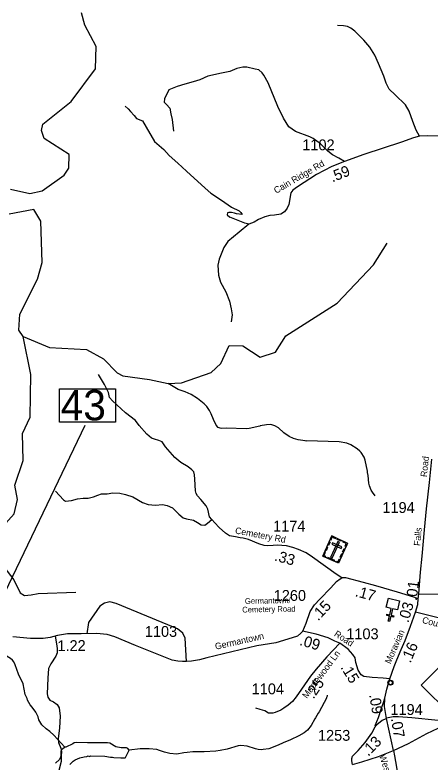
# Model space of a CAD drawing. Extents: x 1248089 to 1457196, y 820910 to 988753.
# Drawn here: x 1350937 to 1355719, y 860169 to 868771 of the extents above; entities that cross this region are included whole.
import ezdxf

# ---------------------------------------------------------------- set-up
doc = ezdxf.new("R2010")
doc.units = 0
for name, color, linetype in [('Exist Civil Demographics Community CELL', 7, 'Continuous'), ('Exist Cultural Cemetery CELL', 7, 'Continuous'), ('Exist Cultural Church CELL', 7, 'Continuous'), ('Exist Hydrographic Creek Single Shore', 7, 'Continuous'), ('Exist Hydrographic Misc Water Feature', 7, 'Continuous'), ('Exist Road Non-System Type 51', 7, 'Continuous'), ('Exist Road Primary NC Attributed', 7, 'Continuous'), ('Exist Road Primary NC Shield CELL', 7, 'Continuous'), ('Exist Road Secondary Structure Standard Bridge Number Label', 7, 'Continuous'), ('Exist Road Secondary Type 10 Attributed', 7, 'Continuous'), ('Exist Road Secondary Type 51 Attributed', 7, 'Continuous'), ('Exist Road Secondary Type 51 Label', 7, 'Continuous'), ('Prop GRAU CAT1 Cell', 7, 'Continuous'), ('Prop Lane Lines', 7, 'Continuous')]:
    doc.layers.add(name, color=color, linetype=linetype)

msp = doc.modelspace()

# ---------------------------------------------------------------- linework, layer by layer
at = {"layer": 'Exist Civil Demographics Community CELL'}
msp.add_lwpolyline([(1355238.4, 861087.2), (1355238.7, 861088.9), (1355239.2, 861090.9), (1355240.1, 861093.1), (1355241, 861094.8), (1355242, 861096.6), (1355243.2, 861098.2), (1355244.4, 861099.5), (1355245.8, 861100.9), (1355247.5, 861102.3), (1355249.1, 861103.4), (1355250.6, 861104.3), (1355252.1, 861105), (1355253.8, 861105.7), (1355255.5, 861106.3), (1355256.8, 861106.6), (1355258.3, 861106.8), (1355259.6, 861107.1), (1355261.5, 861107.2), (1355262.9, 861107.1), (1355264.6, 861107), (1355266.1, 861106.8), (1355267.6, 861106.5), (1355269.1, 861106.1), (1355270.7, 861105.5), (1355272.7, 861104.6), (1355274.6, 861103.5), (1355276.2, 861102.5), (1355277.7, 861101.2), (1355278.7, 861100.3), (1355280, 861098.9), (1355281.2, 861097.5), (1355282.1, 861096.1), (1355283.1, 861094.6), (1355283.8, 861093), (1355284.4, 861091.5), (1355284.9, 861090), (1355285.3, 861088.6), (1355285.6, 861086.7), (1355285.8, 861085.3), (1355285.9, 861083.5), (1355285.9, 861081.7), (1355285.7, 861080), (1355285.4, 861078.3), (1355284.9, 861076.4), (1355284.3, 861074.6), (1355283.6, 861073.1), (1355282.7, 861071.3), (1355281.7, 861069.6), (1355280.6, 861068.2), (1355279.3, 861066.8), (1355277.7, 861065.2), (1355276.2, 861064), (1355274.6, 861062.9), (1355273.3, 861062.2), (1355271.3, 861061.2), (1355269.1, 861060.4), (1355267.3, 861059.9), (1355265.2, 861059.5), (1355263.9, 861059.4), (1355262.5, 861059.3), (1355260.8, 861059.3), (1355259.5, 861059.4), (1355257.8, 861059.6), (1355256, 861060), (1355254.6, 861060.4), (1355253, 861061), (1355251.6, 861061.6), (1355250.4, 861062.3), (1355248.4, 861063.5), (1355246.7, 861064.8), (1355245.2, 861066.2), (1355243.8, 861067.7), (1355242.8, 861068.9), (1355241.9, 861070.2), (1355240.7, 861072.3), (1355240.2, 861073.4), (1355239.6, 861074.6), (1355238.8, 861077.1), (1355238.4, 861079.3), (1355238.2, 861080.9), (1355238.1, 861082.8), (1355238, 861084.2), (1355238.2, 861086.2)], close=True, dxfattribs=at)
msp.add_lwpolyline([(1355238.4, 861087.2), (1355238.7, 861088.9), (1355239.2, 861090.9), (1355240.1, 861093.1), (1355241, 861094.8), (1355242, 861096.6), (1355243.2, 861098.2), (1355244.4, 861099.5), (1355245.8, 861100.9), (1355247.5, 861102.3), (1355249.1, 861103.4), (1355250.6, 861104.3), (1355252.1, 861105), (1355253.8, 861105.7), (1355255.5, 861106.3), (1355256.8, 861106.6), (1355258.3, 861106.8), (1355259.6, 861107.1), (1355261.5, 861107.2), (1355262.9, 861107.1), (1355264.6, 861107), (1355266.1, 861106.8), (1355267.6, 861106.5), (1355269.1, 861106.1), (1355270.7, 861105.5), (1355272.7, 861104.6), (1355274.6, 861103.5), (1355276.2, 861102.5), (1355277.7, 861101.2), (1355278.7, 861100.3), (1355280, 861098.9), (1355281.2, 861097.5), (1355282.1, 861096.1), (1355283.1, 861094.6), (1355283.8, 861093), (1355284.4, 861091.5), (1355284.9, 861090), (1355285.3, 861088.6), (1355285.6, 861086.7), (1355285.8, 861085.3), (1355285.9, 861083.5), (1355285.9, 861081.7), (1355285.7, 861080), (1355285.4, 861078.3), (1355284.9, 861076.4), (1355284.3, 861074.6), (1355283.6, 861073.1), (1355282.7, 861071.3), (1355281.7, 861069.6), (1355280.6, 861068.2), (1355279.3, 861066.8), (1355277.7, 861065.2), (1355276.2, 861064), (1355274.6, 861062.9), (1355273.3, 861062.2), (1355271.3, 861061.2), (1355269.1, 861060.4), (1355267.3, 861059.9), (1355265.2, 861059.5), (1355263.9, 861059.4), (1355262.5, 861059.3), (1355260.8, 861059.3), (1355259.5, 861059.4), (1355257.8, 861059.6), (1355256, 861060), (1355254.6, 861060.4), (1355253, 861061), (1355251.6, 861061.6), (1355250.4, 861062.3), (1355248.4, 861063.5), (1355246.7, 861064.8), (1355245.2, 861066.2), (1355243.8, 861067.7), (1355242.8, 861068.9), (1355241.9, 861070.2), (1355240.7, 861072.3), (1355240.2, 861073.4), (1355239.6, 861074.6), (1355238.8, 861077.1), (1355238.4, 861079.3), (1355238.2, 861080.9), (1355238.1, 861082.8), (1355238, 861084.2), (1355238.2, 861086.2)], close=True, dxfattribs=at)
for centre, radius in [((1355262, 861083.4), 28.8), ((1355262, 861083.4), 28.8), ((1355261.9, 861083.5), 23.4), ((1355261.9, 861083.5), 23.4)]:
    msp.add_circle(centre, radius, dxfattribs=at)
at = {"layer": 'Exist Cultural Cemetery CELL'}
for points in [[(1354587.1, 862773), (1354768.6, 862691.1), (1354663.9, 862459), (1354482.5, 862540.9)], [(1354569.3, 862733.5), (1354579.7, 862728.8), (1354592.9, 862758.2), (1354629.9, 862741.5), (1354634.5, 862751.7), (1354587.1, 862773)], [(1354538.8, 862665.9), (1354556.6, 862705.4), (1354567, 862700.7), (1354549.2, 862661.2)], [(1354674.5, 862701.5), (1354657.4, 862709.1), (1354574.1, 862524.3), (1354591.1, 862516.6)], [(1354596.4, 862694.2), (1354588.7, 862677.2), (1354696, 862628.7), (1354703.7, 862645.8)], [(1354654.6, 862742.5), (1354701.9, 862721.2), (1354697.2, 862710.8), (1354650, 862732.1)], [(1354750.9, 862651.6), (1354740.5, 862656.3), (1354753.7, 862685.6), (1354716.8, 862702.3), (1354721.3, 862712.4), (1354768.7, 862691.1)], [(1354512.6, 862527.3), (1354517.3, 862537.8), (1354497.3, 862546.8), (1354513.9, 862583.7), (1354503.8, 862588.3), (1354482.4, 862541)], [(1354511.2, 862604.7), (1354529, 862644.1), (1354539.4, 862639.5), (1354521.6, 862600)], [(1354710.4, 862589.7), (1354728.2, 862629.1), (1354738.6, 862624.5), (1354720.8, 862585)], [(1354539.5, 862527.7), (1354616.9, 862492.8), (1354612.2, 862482.4), (1354534.9, 862517.3)], [(1354633.7, 862472.7), (1354638.5, 862483.1), (1354658.5, 862474.1), (1354675.1, 862510.9), (1354685.3, 862506.3), (1354663.9, 862459)], [(1354683.3, 862529.6), (1354701.1, 862569.1), (1354711.5, 862564.4), (1354693.7, 862524.9)]]:
    msp.add_lwpolyline(points, close=True, dxfattribs=at)
at = {"layer": 'Exist Cultural Church CELL'}
msp.add_lwpolyline([(1355342.2, 861922.1), (1355286.7, 861934.8), (1355269.6, 861860.6), (1355300.8, 861853.4), (1355297.2, 861837.8), (1355266, 861845), (1355252.6, 861786.4), (1355236.9, 861790), (1355250.4, 861848.6), (1355219.2, 861855.8), (1355222.8, 861871.3), (1355254, 861864.2), (1355271.1, 861938.4), (1355214.9, 861951.4), (1355238.7, 862055.1), (1355366, 862025.9)], close=True, dxfattribs=at)
at = {"layer": 'Exist Hydrographic Creek Single Shore'}
for points in [[(1350885.2, 866764.1), (1351109.2, 866716.9), (1351252.2, 866747), (1351506.2, 866925.7), (1351558.3, 867006.7), (1351561.2, 867164.1), (1351273.2, 867347.2), (1351242.2, 867439.7), (1351260.2, 867514.9), (1351583.2, 867774.4), (1351866.2, 868149.5), (1351872.2, 868408.7), (1351744.2, 868654.1), (1351705.2, 868796.1)], [(1351031.3, 865067.3), (1350983.2, 865143.7), (1350995.2, 865327.3), (1351196.2, 865730.3), (1351250.3, 865919.7), (1351235.2, 866396), (1351155.2, 866532.2), (1350870.2, 866478.7)], [(1351031.3, 865067.3), (1351337.2, 864942.9), (1351762.3, 864917.9), (1351959.2, 864812.2), (1352114.3, 864651.5), (1352180.3, 864617.4), (1352488.3, 864575), (1352701.2, 864526.8), (1352854.3, 864534.9), (1353198.3, 864652.7), (1353309.3, 864758.9), (1353405.3, 864963.7), (1353564.3, 864960.5), (1353761.2, 864831.9), (1353937.3, 864887.3), (1354058.3, 865075.4), (1354650.3, 865454.1), (1355068.3, 865895.5), (1355224.3, 866141.8)], [(1350118.3, 862209.9), (1350114.3, 862410.2), (1350191.3, 862533.3), (1350379.2, 862729.8), (1350522.2, 862792.6), (1350765.2, 862846.9), (1350928.2, 863027.4), (1350965.2, 863190.7), (1350935.2, 863358.9), (1351033.2, 863642.5), (1351023.3, 863951.2), (1351111.2, 864139.8), (1351122.2, 864632), (1351031.3, 865067.3)]]:
    msp.add_lwpolyline(points, dxfattribs=at)
at = {"layer": 'Exist Hydrographic Misc Water Feature'}
for points in [[(1355088.6, 863236.1), (1355055.6, 863276.9), (1355040.1, 863301.2), (1355021.2, 863349.7), (1355014, 863381.8), (1355005.9, 863470), (1354998.7, 863502.1), (1354999, 863518.1), (1354972, 863646.8), (1354958.6, 863679.1), (1354925.9, 863733.8), (1354910.2, 863750.2), (1354878.9, 863777), (1354807.8, 863820.7), (1354760.4, 863841.8), (1354672.6, 863855.8), (1354294.8, 863866.9), (1354288.7, 863865), (1354280.8, 863869.2), (1354201, 863879.1), (1354145.4, 863894.4), (1354097.8, 863917.5), (1354034.9, 863961), (1353972.1, 864018.5), (1353932.6, 864039.4), (1353884.9, 864054.6), (1353836.9, 864053.7), (1353762.6, 864041.5), (1353756.5, 864037.7), (1353635.8, 864010.5), (1353603.8, 864007.3), (1353371.8, 864014.8), (1353315.8, 864010.1), (1353299.8, 864012.6), (1353278, 864023), (1353256.6, 864047.5), (1353224.1, 864112.3), (1353199.5, 864176.9), (1353180.4, 864217.3), (1353149.5, 864264.1), (1353118.2, 864294.8), (1353039.6, 864356.7), (1352968.6, 864402.4), (1352897.2, 864432.1), (1352817.8, 864460), (1352701.2, 864526.8)], [(1351511.8, 860340.9), (1351387.2, 860478.5), (1351340.2, 860521.7), (1351298.9, 860552.6), (1351247.9, 860599.8), (1351234.3, 860616.2), (1351211.2, 860656.7), (1351203.9, 860688.9), (1351177.2, 860745.5), (1351134.5, 860802.5), (1351111, 860827.1), (1351080.3, 860883.8), (1351076.7, 860899.9), (1351055.8, 860948.4), (1351030.6, 861069), (1350977, 861182.3), (1350941.5, 861287), (1350924.2, 861323.4), (1350910.7, 861341.8), (1350887.1, 861362.3), (1350816.1, 861404.3)], [(1354532.4, 860937.6), (1354534.3, 860929.5), (1354525.9, 860913.7), (1354525.7, 860905.7), (1354442.1, 860747.7), (1354429.7, 860732.1), (1354400.5, 860676.8), (1354392.3, 860668.9), (1354350.5, 860590), (1354309.2, 860537), (1354268.5, 860505.9), (1354207.7, 860469.4), (1354110.6, 860423.7), (1354027.9, 860391.7), (1353971.2, 860363), (1353860.3, 860321.6), (1353796.1, 860313.1), (1353772, 860311.8), (1353740.1, 860314.5), (1353708.2, 860321.2), (1353613, 860353.5), (1353541.1, 860361.2), (1353507, 860356.1), (1353380.1, 860319.1), (1353299.7, 860301), (1353251.5, 860294.2), (1353115.3, 860287.4), (1352987.3, 860288.4), (1352923.1, 860278), (1352883, 860274.9), (1352802.6, 860260.8), (1352722.7, 860266.8), (1352659.1, 860282.3), (1352603.5, 860303.6), (1352571.7, 860312.3), (1352484, 860322.5), (1352379.9, 860320.9), (1352253.6, 860306.6)], [(1352253.6, 860306.6), (1352238, 860326.3), (1352222.1, 860332.6), (1352160.1, 860332.1), (1352100.3, 860343.6), (1352029.3, 860385.2), (1352005.4, 860391.8), (1351773.4, 860391.4), (1351645.4, 860396.4), (1351621.3, 860391), (1351605, 860379.4), (1351524.1, 860341.3), (1351511.8, 860340.9)], [(1351511.8, 860340.9), (1351506, 860333.7), (1351475.4, 860308.4), (1351465.1, 860292.7), (1351464.6, 860270.7), (1351471.1, 860206.6), (1351469, 860200.7), (1351470.4, 860174.6), (1351442, 860071.3)], [(1351571.6, 860140.2), (1351606.4, 860179.3), (1351632.9, 860196.7), (1351683.4, 860219.5), (1351733.7, 860230.3), (1351765.8, 860233.6), (1351781.9, 860239.1), (1351797.8, 860234.8), (1351811.9, 860240.4), (1351973.9, 860236.6), (1352037.7, 860227.1), (1352061.7, 860226.5), (1352077.6, 860222.1), (1352157.4, 860216.3), (1352205.5, 860219.1), (1352211.6, 860221), (1352253.6, 860306.6)]]:
    msp.add_lwpolyline(points, dxfattribs=at)
at = {"layer": 'Exist Road Non-System Type 51'}
for points in [[(1355599.1, 867375.3), (1355557.9, 867446.4), (1355518.9, 867545.6), (1355479.8, 867662.8), (1355437.8, 867735), (1355317.7, 867852.2), (1355248.6, 867918.3), (1355212.5, 867984.4), (1355185.5, 868065.6), (1355125.4, 868212.9), (1355083.4, 868309), (1355026.3, 868399.2), (1354954.3, 868480.4), (1354852.1, 868585.6), (1354807.1, 868618.6), (1354768, 868636.6), (1354723, 868645.7), (1354653.9, 868648.7)], [(1354733.8, 867085.4), (1354669.4, 867120.3), (1354594.3, 867162.4), (1354540.2, 867204.5), (1354456.1, 867288.7), (1354372, 867348.8), (1354336, 867366.8), (1354170.8, 867429.9), (1354092.7, 867484), (1354032.6, 867583.2), (1353966.6, 867715.4), (1353852.4, 867989), (1353804.4, 868076.1), (1353783.4, 868106.2), (1353747.3, 868139.2), (1353705.3, 868148.2), (1353609.6, 868171.1), (1353561.6, 868168.1), (1353492.5, 868153.1), (1353414.4, 868120), (1353297.3, 868095.9), (1353246.2, 868083.9), (1353159.1, 868065.9), (1353066, 868023.8), (1352990.9, 868002.8), (1352894.8, 867975.7), (1352807.7, 867945.7), (1352711.6, 867909.6), (1352660.6, 867804.4), (1352657.6, 867768.3), (1352684.6, 867741.3), (1352720.6, 867699.2), (1352732.6, 867633.1), (1352747.7, 867567), (1352765.7, 867431.7)], [(1352207.1, 867721.4), (1352243.1, 867688.4), (1352267.1, 867661.3), (1352312.2, 867613.2), (1352336.2, 867577.2), (1352405.3, 867553.1), (1352450.3, 867478), (1352543.4, 867315.7), (1352651.6, 867222.5), (1352714.6, 867153.4), (1352813.7, 867066.2), (1352912.9, 866973), (1353129.1, 866777.7), (1353194.6, 866718.9), (1353317.7, 866637.7), (1353431.9, 866559.6), (1353522, 866514.5), (1353540, 866496.4), (1353555, 866475.4)], [(1353555, 866475.4), (1353488.9, 866481.4), (1353464.9, 866490.4), (1353431.9, 866496.4), (1353401.8, 866496.4), (1353386.8, 866493.4), (1353380.8, 866469.4), (1353413.1, 866442)], [(1353631, 866363.9), (1353519.2, 866269.8), (1353390.1, 866161.6), (1353345, 866095.5), (1353290.9, 865960.3), (1353272.9, 865891.1), (1353281.9, 865773.9), (1353306, 865695.8), (1353366, 865584.6), (1353408.1, 865476.4), (1353429.1, 865389.2), (1353438.1, 865320.1), (1353429.1, 865235.9)], [(1353178.6, 862991.1), (1353159.5, 863080.2), (1353141.8, 863120.1), (1353077.6, 863190.9), (1353040, 863235.2), (1353024.5, 863259.6), (1353017.9, 863292.8), (1353011.2, 863425.7), (1353006.8, 863474.4), (1352997.9, 863509.9), (1352973.6, 863534.2), (1352933.8, 863569.7), (1352849.7, 863618.4), (1352778.8, 863676), (1352672.6, 863797.8), (1352633.1, 863854.5), (1352593.3, 863872.2), (1352546.8, 863885.5), (1352511.4, 863896.6), (1352456, 863943.1), (1352369.7, 864042.8), (1352327.7, 864100.4), (1352212.6, 864189), (1352060.5, 864329.5), (1352027.3, 864365), (1352016.2, 864422.5), (1351967.5, 864515.6), (1351901.1, 864630.7)], [(1351405.2, 863286.8), (1351498.1, 863187.1), (1351518, 863173.8), (1351588.8, 863180.5), (1351657.5, 863200.4), (1351721.6, 863207), (1351781.4, 863207), (1351827.9, 863218.1), (1351841.2, 863224.8), (1351892.1, 863242.5), (1351936.3, 863258), (1351998.3, 863255.8), (1352064.7, 863269.1), (1352144.4, 863264.6), (1352210.8, 863249.1), (1352297.1, 863224.8), (1352407.7, 863156.1), (1352471.9, 863134), (1352556, 863125.1), (1352635.7, 863134), (1352691, 863122.9), (1352753, 863096.3), (1352826, 863023.2), (1352875.7, 862981.4), (1352913.3, 862968.1), (1352995.2, 862952.6), (1353041.7, 862926), (1353083.7, 862899.5), (1353123.5, 862897.2), (1353154.5, 862919.4), (1353205.4, 862961.5)], [(1350660.7, 862252.6), (1350657.9, 862426.4), (1350661.3, 862457.2), (1350695.4, 862467.4), (1350763.6, 862460.6), (1350811.4, 862416.2), (1350923.9, 862266), (1350999, 862115.8), (1351046.7, 862085.1), (1351125.2, 862095.3), (1351203.7, 862109), (1351640.3, 862126)], [(1352913.3, 861328), (1352898.4, 861597.1), (1352871.1, 861655.2), (1352809.7, 861702.9), (1352103.6, 861996.5), (1352028.6, 862013.6), (1351970.6, 861999.9), (1351916, 861962.4), (1351783, 861774.6), (1351765.9, 861644.9)], [(1351400.4, 861619.1), (1351417.5, 861530.8), (1351424.9, 861476.8), (1351422.4, 861427.8), (1351407.7, 861388.6), (1351351.4, 861300.3), (1351324.4, 861246.4), (1351314.6, 861133.6), (1351309.7, 860954.6), (1351314.6, 860915.3), (1351339.1, 860881), (1351380.8, 860861.4), (1351422.4, 860832), (1351446.9, 860795.2), (1351459.2, 860697.1), (1351451.8, 860562.2), (1351437.1, 860437.2), (1351439.6, 860395.5), (1351466.5, 860329.3), (1351473.9, 860287.6), (1351471.4, 860245.9), (1351449.4, 860196.9), (1351405.3, 860157.6)], [(1355088.2, 860588.4), (1355125.4, 860683.5), (1355161.2, 860788.6), (1355181.1, 860856.6), (1355196.6, 860903.9)], [(1356091.9, 860630.9), (1355812.5, 860648.8), (1355510.7, 860680.1), (1355354.2, 860691.3), (1355293.9, 860689.1), (1355217.9, 860673.4)]]:
    msp.add_lwpolyline(points, dxfattribs=at)
at = {"layer": 'Exist Road Primary NC Attributed'}
for points in [[(1355298.7, 860301.7), (1355470, 860382.6), (1355681.8, 860499), (1355811.2, 860558.3), (1355897.6, 860588.5), (1356022.4, 860613.2), (1356097.9, 860617.4), (1356169.5, 860613.8), (1356318.9, 860597.6)], [(1354827.3, 860141.6), (1354933, 860173.1), (1355123.6, 860231.6), (1355298.7, 860301.7)]]:
    msp.add_lwpolyline(points, dxfattribs=at)
at = {"layer": 'Exist Road Primary NC Shield CELL'}
msp.add_lwpolyline([(1355616.4, 861055.9), (1355949.4, 861388.9), (1356282.4, 861055.9), (1355949.4, 860722.9)], close=True, dxfattribs=at)
at = {"layer": 'Exist Road Secondary Structure Standard Bridge Number Label'}
msp.add_line((1350655.5, 861776.7), (1351747.8, 864049.4), dxfattribs=at)
msp.add_lwpolyline([(1351451.8, 864465.9), (1352095.9, 864465.9), (1352095.9, 864083.6), (1351451.8, 864083.6)], close=True, dxfattribs=at)
at = {"layer": 'Exist Road Secondary Type 10 Attributed'}
msp.add_lwpolyline([(1354138.1, 862639.6), (1354066.8, 862659.2), (1353959, 862667), (1353912.1, 862662.3), (1353851.1, 862659.2), (1353807.4, 862662.3), (1353746.4, 862681.1), (1353627.7, 862731.1), (1353565.2, 862748.3), (1353532.3, 862751.5), (1353477.7, 862760.8), (1353408.9, 862774.9), (1353362, 862804.6), (1353291.7, 862870.3), (1353240.1, 862923.5), (1353205.4, 862961.5), (1353178.6, 862991.1)], dxfattribs=at)
at = {"layer": 'Exist Road Secondary Type 51 Attributed'}
for points in [[(1355811.6, 867375.3), (1355690.5, 867380.7), (1355599.1, 867375.3), (1355526.4, 867356.5), (1355391.9, 867308.1), (1354957.1, 867163.5), (1354733.8, 867085.4), (1354585.9, 867026.2), (1354411, 866934.6), (1354193.2, 866792), (1354139.4, 866754.3), (1354115.2, 866722), (1354091, 866587.4), (1354074.8, 866547), (1354042.5, 866503.9), (1353999.5, 866477), (1353926.9, 866466.2), (1353873.1, 866463.6), (1353816.6, 866447.4), (1353744, 866415.1), (1353692.9, 866385.5), (1353631, 866363.9), (1353585.3, 866374.7), (1353413.1, 866442)], [(1355587.9, 862106.5), (1355609.4, 862354.2), (1355628.3, 862541.3), (1355655.2, 862842.8), (1355679.4, 863085), (1355711.2, 863386.9), (1355738.1, 863656.1)], [(1354704.4, 862291.6), (1354636.7, 862331.7), (1354366.3, 862527.2), (1354292.9, 862578.8), (1354203.8, 862616.4), (1354138.1, 862639.6)], [(1355587.9, 862106.5), (1355848.8, 862101.7), (1355920.3, 862099.6), (1355952.8, 862108.2), (1355970.1, 862123.4), (1355972.3, 862162.4), (1355989.6, 862325.1), (1356009.1, 862494.2), (1356020.1, 862598.7)], [(1354252, 861674.5), (1354290.9, 861768.4), (1354339.6, 861903.5), (1354388.3, 861978.8), (1354448.1, 862043), (1354574.2, 862173.7), (1354642.8, 862246.8), (1354684.9, 862277.8), (1354704.4, 862291.6)], [(1355581.2, 862050), (1355533.6, 862069.7), (1355342.9, 862124.4), (1355092.9, 862196.4), (1354950.7, 862235.5), (1354750.6, 862288.6), (1354704.4, 862291.6)], [(1355581.2, 862050), (1355587.9, 862106.5)], [(1355552.1, 861894), (1355578.1, 861985.1), (1355581.2, 862050)], [(1355254.6, 861128.8), (1355306.1, 861271.2), (1355335.8, 861345), (1355387.7, 861463.7), (1355431.5, 861570.7), (1355493.9, 861733.9), (1355552.1, 861894)], [(1356115.5, 861753.1), (1355844.6, 861820.3), (1355552.1, 861894)], [(1354252, 861674.5), (1354231.8, 861654.2), (1354193, 861619.2), (1354131.5, 861597.8), (1353943.8, 861542.4), (1353723.8, 861507.3), (1353146.8, 861369.8), (1353063.1, 861345.5), (1352972.7, 861330.7), (1352913.3, 861328), (1352867.4, 861328), (1352812.1, 861329.3), (1352749.6, 861341.1), (1352327.1, 861509.9), (1352086.8, 861612.6), (1351999.9, 861636.8), (1351875.7, 861649), (1351701.6, 861646.3), (1351543.6, 861644.9), (1351428.9, 861627.4), (1351342.5, 861604.4), (1351261.5, 861593.6), (1351118.1, 861593.4), (1350913, 861612.3)], [(1354680.9, 861536.3), (1354623.2, 861562.4), (1354543.6, 861601.5), (1354407.2, 861642.1), (1354285.8, 861669.1), (1354252, 861674.5)], [(1354680.9, 861536.3), (1354531.4, 861380), (1354408.7, 861238.1), (1354343.4, 861160), (1354239.9, 861008.6), (1354178.6, 860920.1), (1354135.6, 860867.5), (1354086.2, 860826.1), (1354033.6, 860789.4), (1354001.8, 860767.1), (1353936.4, 860740), (1353906.2, 860730.4), (1353858.4, 860733.6), (1353815.4, 860759.1), (1353762.8, 860775), (1353711.4, 860788.8)], [(1355254.6, 861128.8), (1355177.8, 861134.6), (1355052, 861141), (1354954.8, 861155.3), (1354926.2, 861174.4), (1354892.7, 861228.6), (1354865.6, 861314.7), (1354857.7, 861368.9), (1354829, 861407.2), (1354776.4, 861469.3), (1354680.9, 861536.3)], [(1355218.3, 860670.9), (1355195.3, 860807.6), (1355196.6, 860903.9), (1355222.4, 861008.9), (1355254.6, 861128.8)], [(1354972.7, 860396.3), (1355048.2, 860503.7), (1355087.3, 860573.5), (1355106.1, 860600.7), (1355167.3, 860651.7), (1355218.3, 860670.9)], [(1355298.7, 860301.7), (1355218.3, 860670.9)], [(1354827.3, 860141.6), (1354816.7, 860183.5), (1354816.7, 860209.3), (1354827, 860236.7), (1354892.1, 860301.9), (1354972.7, 860396.3)], [(1355298.7, 860301.7), (1355308.3, 860241.7), (1355348.1, 860021.8), (1355386.3, 859830.9), (1355428.8, 859678.9), (1355446, 859596.6), (1355466.5, 859541.6), (1355492.8, 859471.1), (1355500.5, 859451.3), (1355531.7, 859394), (1355563.7, 859338.5)]]:
    msp.add_lwpolyline(points, dxfattribs=at)

# ---------------------------------------------------------------- texts
at = {"layer": 'Exist Road Secondary Structure Standard Bridge Number Label'}
msp.add_text('43', height=350, dxfattribs=at).set_placement((1351464.3, 864103.4))
at = {"layer": 'Exist Road Secondary Type 51 Label'}
for s, height, rotation, p in [('Cain Ridge Rd', 75, 30.24909, (1353946.5, 866710.9)), (' Falls                     Road', 75, 84.36277, (1355602, 862627.5)), ('Cemetery Rd', 75, 349.27845, (1353468.8, 862801.3)), ('Germantown/ ', 65.617, 1.09858, (1353587.2, 861989.9)), ('Cemetery Road', 65.617, 1.09858, (1353555.9, 861890.8)), ('Country Club Rd', 75, 344.99193, (1355622.1, 861772.7)), ('Germantown ', 75, 12.76877, (1353251.2, 861461.8)), ('Road', 75, 326.5279, (1354607.2, 861627.1)), ('Moravian ', 75, 66.33675, (1355262.5, 861293.4)), ('Maplewood Ln', 75, 53.34998, (1354299.9, 860895.7)), ('West Brocktown Rd', 75, 288.43858, (1355132, 860240.6))]:
    msp.add_text(s, height=height, rotation=rotation, dxfattribs=at).set_placement(p)
at = {"layer": 'Prop GRAU CAT1 Cell'}
for s, rotation, p in [('.59', 21.81685, (1354594.1, 866841.8)), ('.33', 344.66329, (1353918.7, 862491.3)), ('.01', 83.21676, (1355565.4, 862021)), ('.17', 344.62698, (1354848.2, 862080.8)), ('.15', 47.06558, (1354430.7, 861788.4)), ('.03', 74.0666, (1355469, 861766.8)), ('1.22', 0.4901, (1351427.7, 861446)), ('.09', 343.44476, (1354207.9, 861518.9)), ('.16', 67.02745, (1355493, 861301.7)), ('.15', 301.68166, (1354683.3, 861260.1)), ('.25', 55.64076, (1354376.1, 860888.7)), ('.09', 279.54479, (1355017.1, 860943.1)), ('.07', 279.54479, (1355267.7, 860670)), ('.13', 45.02631, (1355006, 860229.1))]:
    msp.add_text(s, height=125, rotation=rotation, dxfattribs=at).set_placement(p)
at = {"layer": 'Prop Lane Lines'}
for s, p in [('1102', (1354247.5, 867213)), ('1194', (1355170.1, 863037.3)), ('1174', (1353911.2, 862823.5)), ('1260', (1353918.1, 862024.8)), ('1103', (1352433.8, 861610.6)), ('1103', (1354754.3, 861583.2)), ('1104', (1353664.5, 860949.4)), ('1194', (1355262.4, 860711.3)), ('1253', (1354428.1, 860414.1))]:
    msp.add_text(s, height=125, dxfattribs=at).set_placement(p)

doc.saveas('drawing.dxf')
